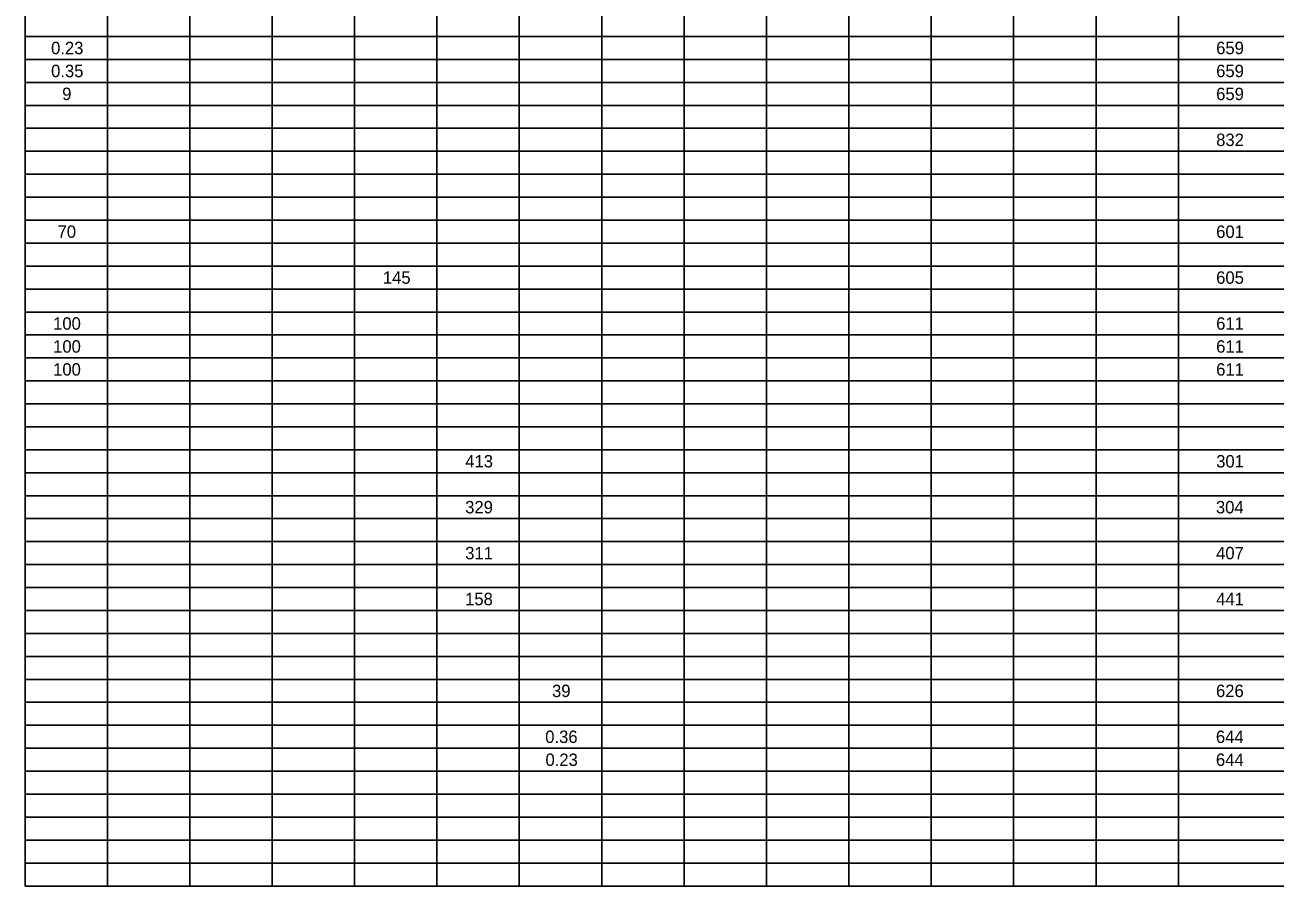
# Model space of a CAD drawing. Extents: x -31.7 to 37.3, y 0 to 22.
# Drawn here: x -31.71 to -16.46, y 0.32 to 10.82 of the extents above; entities that cross this region are included whole.
import ezdxf

# ---------------------------------------------------------------- set-up
doc = ezdxf.new("R2010")
doc.units = 0
doc.layers.add('Default', color=7, linetype='Continuous')

msp = doc.modelspace()

# ---------------------------------------------------------------- linework, layer by layer
at = {"layer": 'Default'}
for p, q in [((-31.705, 21.321), (-31.705, 0.321)), ((-18.644, 21.321), (-18.644, 0.321)), ((-17.639, 21.321), (-17.639, 0.321)), ((-30.7, 20.761), (-30.7, 0.321)), ((-29.696, 20.761), (-29.696, 0.321)), ((-28.691, 20.761), (-28.691, 0.321)), ((-27.686, 20.761), (-27.686, 0.321)), ((-26.682, 20.761), (-26.682, 0.321)), ((-25.677, 20.761), (-25.677, 0.321)), ((-24.672, 20.761), (-24.672, 0.321)), ((-23.668, 20.761), (-23.668, 0.321)), ((-22.663, 20.761), (-22.663, 0.321)), ((-21.658, 20.761), (-21.658, 0.321)), ((-20.653, 20.761), (-20.653, 0.321)), ((-19.649, 20.761), (-19.649, 0.321)), ((-31.705, 10.681), (-1.202, 10.681)), ((-31.705, 10.401), (-1.202, 10.401)), ((-31.705, 10.121), (-1.202, 10.121)), ((-31.705, 9.841), (-1.202, 9.841)), ((-31.705, 9.561), (-1.202, 9.561)), ((-31.705, 9.281), (-1.202, 9.281)), ((-31.705, 9.001), (-1.202, 9.001)), ((-31.705, 8.721), (-1.202, 8.721)), ((-31.705, 8.441), (-1.202, 8.441)), ((-31.705, 8.161), (-1.202, 8.161)), ((-31.705, 7.881), (-1.202, 7.881)), ((-31.705, 7.601), (-1.202, 7.601)), ((-31.705, 7.321), (-1.202, 7.321)), ((-31.705, 7.041), (-1.202, 7.041)), ((-31.705, 6.761), (-1.202, 6.761)), ((-31.705, 6.481), (-1.202, 6.481)), ((-31.705, 6.201), (-1.202, 6.201)), ((-31.705, 5.921), (-1.202, 5.921)), ((-31.705, 5.641), (-1.202, 5.641)), ((-31.705, 5.361), (-1.202, 5.361)), ((-31.705, 5.081), (-1.202, 5.081)), ((-31.705, 4.801), (-1.202, 4.801)), ((-31.705, 4.521), (-1.202, 4.521)), ((-31.705, 4.241), (-1.202, 4.241)), ((-31.705, 3.961), (-1.202, 3.961)), ((-31.705, 3.681), (-1.202, 3.681)), ((-31.705, 3.401), (-1.202, 3.401)), ((-31.705, 3.121), (-1.202, 3.121)), ((-31.705, 2.841), (-1.202, 2.841)), ((-31.705, 2.561), (-1.202, 2.561)), ((-31.705, 2.281), (-1.202, 2.281)), ((-31.705, 2.001), (-1.202, 2.001)), ((-31.705, 1.721), (-1.202, 1.721)), ((-31.705, 1.441), (-1.202, 1.441)), ((-31.705, 1.161), (-1.202, 1.161)), ((-31.705, 0.881), (-1.202, 0.881)), ((-31.705, 0.601), (-1.202, 0.601)), ((-31.705, 0.321), (-1.202, 0.321))]:
    msp.add_line(p, q, dxfattribs=at)

# ---------------------------------------------------------------- texts
for s, height, p in [('0.23', 0.1515, (-31.387, 10.465)), ('659', 0.1515, (-17.179, 10.465)), ('0.35', 0.1515, (-31.387, 10.185)), ('659', 0.1515, (-17.179, 10.185)), ('9', 0.152, (-31.252, 9.905)), ('659', 0.1515, (-17.179, 9.905)), ('832', 0.1515, (-17.179, 9.345)), ('70', 0.1515, (-31.308, 8.225)), ('601', 0.1515, (-17.179, 8.225)), ('145', 0.1515, (-27.341, 7.665)), ('605', 0.1515, (-17.179, 7.665)), ('100', 0.1515, (-31.362, 7.105)), ('611', 0.1515, (-17.179, 7.105)), ('100', 0.1515, (-31.362, 6.825)), ('611', 0.1515, (-17.179, 6.825)), ('100', 0.1515, (-31.362, 6.545)), ('611', 0.1515, (-17.179, 6.545)), ('413', 0.1515, (-26.336, 5.425)), ('301', 0.1515, (-17.179, 5.425)), ('329', 0.1515, (-26.337, 4.865)), ('304', 0.1515, (-17.182, 4.865)), ('311', 0.1515, (-26.337, 4.305)), ('407', 0.1515, (-17.18, 4.305)), ('158', 0.1515, (-26.338, 3.745)), ('441', 0.1515, (-17.179, 3.745)), ('39', 0.1515, (-25.278, 2.625)), ('626', 0.1515, (-17.181, 2.625)), ('0.36', 0.1515, (-25.361, 2.065)), ('644', 0.1515, (-17.182, 2.065)), ('0.23', 0.1515, (-25.358, 1.785)), ('644', 0.1515, (-17.182, 1.785))]:
    msp.add_text(s, height=height, dxfattribs=at).set_placement(p)

doc.saveas('drawing.dxf')
